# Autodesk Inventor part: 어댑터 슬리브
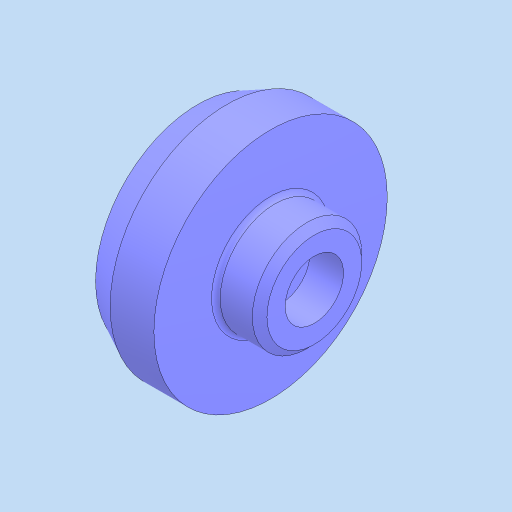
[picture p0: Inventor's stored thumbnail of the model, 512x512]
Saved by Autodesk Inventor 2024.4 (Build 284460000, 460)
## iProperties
Created: 2026-07
Part Number: 어댑터 슬리브
Material: 강철, 탄소
Document SubType Name: Modeling
Designer: home
Density: 7.87 g/cm^3
Appearance: 기본값
Author: jhkim
Sending System: Autodesk Inventor 2027
Preprocessor: ST-DEVELOPER v20.1
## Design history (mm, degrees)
feature "솔리드1"
node "솔리드2"
